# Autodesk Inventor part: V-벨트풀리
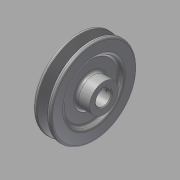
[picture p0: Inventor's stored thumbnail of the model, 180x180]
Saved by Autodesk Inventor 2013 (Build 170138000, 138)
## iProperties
Created: 2015-09
Part Number: V-벨트풀리
Material: 강철, 연강
Document SubType Name: Modeling
Designer: mduedu
Density: 1 g/cm^3
Author: mduedu
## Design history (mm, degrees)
sketch "스케치1"
  geometry: L1 (-10, 0)-(10, 0); L2 (-10, 0)-(-10, 48); L3 (-10, 48)-(-5.976, 48); L4 (-5.976, 48)-(-2.154, 35.5); L5 (-2.154, 35.5)-(2.154, 35.5); L6 (2.154, 35.5)-(5.976, 48); L7 (5.976, 48)-(10, 48); L8 (10, 48)-(10, 0); L9 (0, 0)-(0, 35.5); L10 (-10, 43.5)-(10, 43.5); 3 further points
  constraints: 20 end point, 6 point on line, 3 perpendicular, 2 midpoint, 2 parallel, 2 symmetric about line, 1 coincident, 1 collinear, 1 equal length, 1 horizontal, 1 vertical, 1 vertical alignment
  dimensions: "d0" = 20 distance between parallel lines of L8 L2; "d2" = 96 diameter of L3 L1; "d3" = 87 diameter of L10 L1; "d4" = 4.5 distance between parallel lines of L10 L3 (derived); "d5" = 8 distance between parallel lines of L5 L10; "d6" = 9.2 distance of point (4.6, 43.5) point (-4.6, 43.5); "d7" = 34 deg angle of L6 L4
revolve "회전1" sketch "스케치1" stored, may be unused: angle "d8" = 90 deg
sketch "스케치2"
  geometry: C1 r 16 at (0, 0); 1 further point
  constraints: 1 centre point, 1 coincident
  dimensions: "d9" = 32 diameter of C1
extrude "돌출1" join sketch "스케치2" distance "d10" = 11; taper "d11" = 0 deg
fillet "모깎기1" dims "d12" = 1, "d13" = 0.5, "d14" = 2
sketch "스케치3"
  geometry: C1 r 16 at (0, 0) reference; C2 r 32 at (0, 0); 1 further point
  constraints: 1 centre point, 1 coincident
  dimensions: "d15" = 64 diameter of C2
extrude "돌출2" cut sketch "스케치3" distance "d16" = 4; taper "d17" = 0 deg
fillet "모깎기2" dims "d18" = 3
fillet "모깎기3" dims "d19" = 3
fillet "모깎기4" dims "d20" = 3
sketch "스케치4"
  geometry: C1 r 8.5 at (0, 0); 1 further point
  constraints: 1 centre point, 1 coincident
  dimensions: "d21" = 17 diameter of C1
extrude "돌출3" cut sketch "스케치4" stored distance "d22" = 4; taper "d23" = 0 deg
sketch "스케치5"
  geometry: L1 (-2.5, 8.124)-(2.5, 8.124); L2 (2.5, 8.124)-(2.5, 10.8); L3 (2.5, 10.8)-(-2.5, 10.8); L4 (-2.5, 10.8)-(-2.5, 8.124); A1 r 8.5 centre (0, 0) between (-2.5, 8.124) and (2.5, 8.124) reference; 2 further points
  constraints: 8 end point, 3 point on circle, 2 parallel, 1 horizontal, 1 perpendicular, 1 vertical alignment
  dimensions: "d24" = 5 distance of L2.end L3.end; "d26" = 19.3 distance from line of L3 point (0, -8.5)
extrude "돌출4" cut sketch "스케치5" stored distance "d27" = 4; taper "d28" = 0 deg
chamfer "모따기1" distance "d29" = 1; stored, may be unused: second distance "d30" = 2, angle "d31" = 45 deg
node "작업 평면1"
sketch "스케치6"
  geometry: L1 (-11, 16)-(-11, -16) reference; 2 further points
  constraints: 1 horizontal alignment
  dimensions: "d32" = 5 distance from line of point (-6, 0) L1
hole "구멍1" sketch "스케치6" at (-6, 0) diameter "d33" = 3.242; stored, may be unused: countersink angle "d37" = 90 deg, drill point angle "d39" = 118 deg; dims "d34" = 6, "d35" = 4, "d36" = 2, "d38" = 8
node "솔리드1"
mirror "대칭1"
